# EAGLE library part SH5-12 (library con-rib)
RIBBON CABLE CONNECTOR Flachstecker / Faston
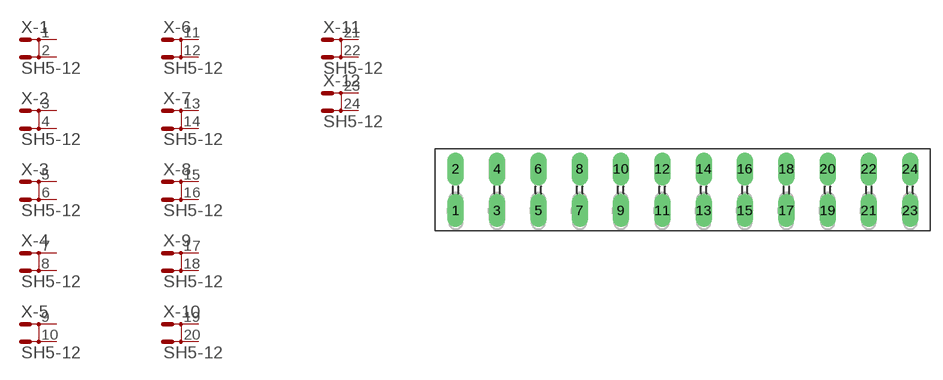
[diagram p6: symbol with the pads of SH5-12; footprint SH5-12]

Designator prefix X; gates -1=MD -2=MD -3=MD -4=MD -5=MD -6=MD -7=MD -8=MD -9=MD -10=MD -11=MD -12=MD

## SH5-12  [SH5-12]
1  -1:1  pas
2  -1:2  pas
3  -2:1  pas
4  -2:2  pas
5  -3:1  pas
6  -3:2  pas
7  -4:1  pas
8  -4:2  pas
9  -5:1  pas
10  -5:2  pas
11  -6:1  pas
12  -6:2  pas
13  -7:1  pas
14  -7:2  pas
15  -8:1  pas
16  -8:2  pas
17  -9:1  pas
18  -9:2  pas
19  -10:1  pas
20  -10:2  pas
21  -11:1  pas
22  -11:2  pas
23  -12:1  pas
24  -12:2  pas

## Footprint SH5-12 (pad centres in mm)
RIBBON CABLE CONNECTOR Flachstecker / Faston
drill 1.321 long: 1 -27.508,-2.515; 2 -27.508,2.515; 3 -22.504,-2.515; 4 -22.504,2.515; 5 -17.501,-2.515; 6 -17.501,2.515; 7 -12.497,-2.515; 8 -12.497,2.515; 9 -7.518,-2.515; 10 -7.518,2.515; 11 -2.515,-2.515; 12 -2.515,2.515; 13 2.515,-2.515; 14 2.515,2.515; 15 7.493,-2.515; 16 7.493,2.515; 17 12.522,-2.515; 18 12.522,2.515; 19 17.526,-2.515; 20 17.526,2.515; 21 22.504,-2.515; 22 22.504,2.515; 23 27.508,-2.515; 24 27.508,2.515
